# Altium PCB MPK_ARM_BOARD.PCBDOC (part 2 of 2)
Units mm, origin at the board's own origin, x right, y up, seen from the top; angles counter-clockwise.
Board outline 120 x 100 mm, 2 copper layers (Top Layer, Bottom Layer); 129 components, 139 nets, 526 pads, 161 vias.
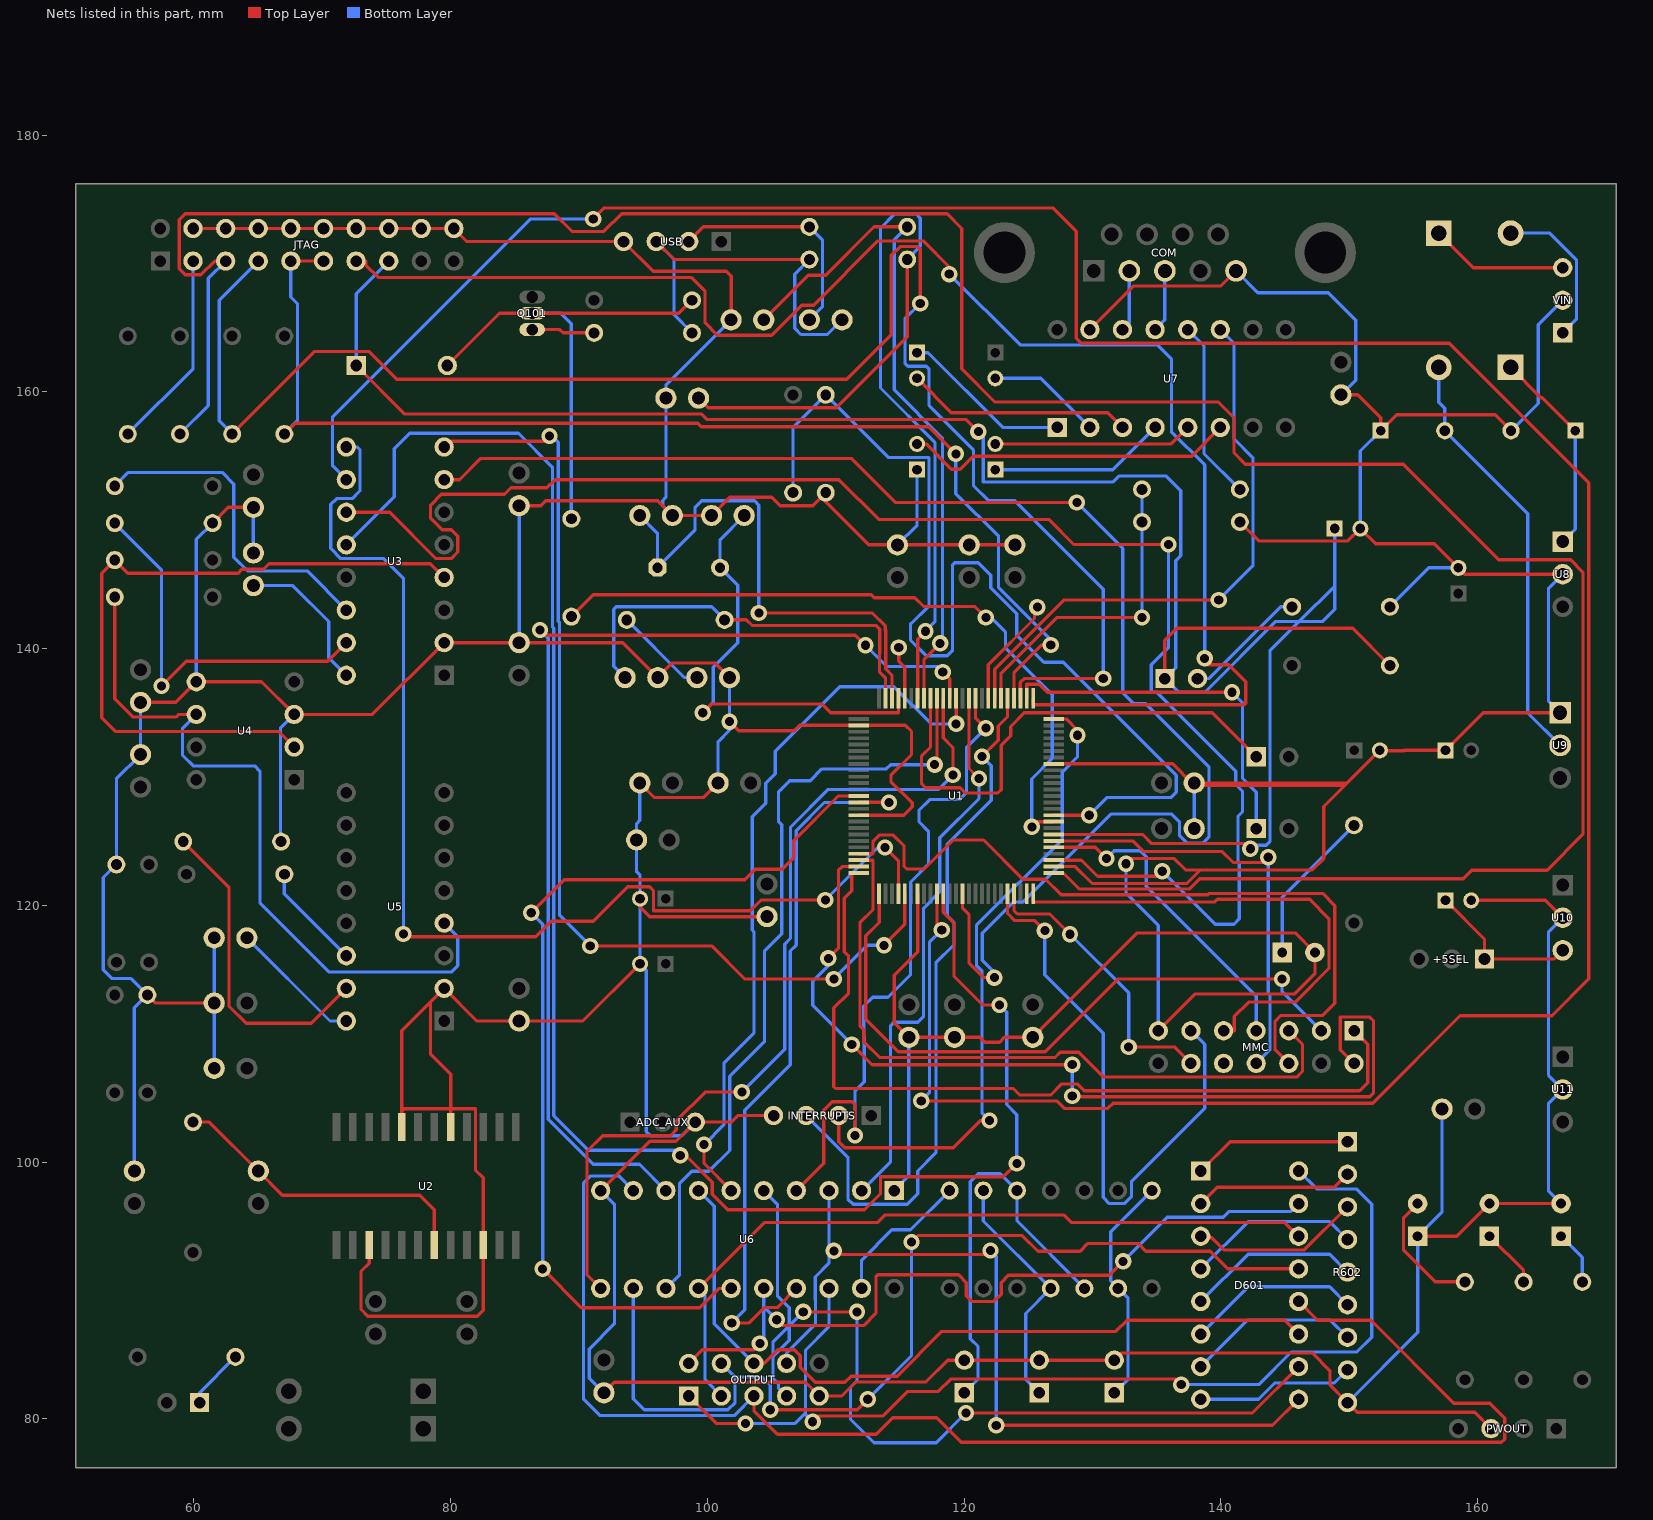
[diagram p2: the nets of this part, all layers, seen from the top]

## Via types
v1: diameter 1.27, hole 0.711, Top Layer to Bottom Layer, 161 vias

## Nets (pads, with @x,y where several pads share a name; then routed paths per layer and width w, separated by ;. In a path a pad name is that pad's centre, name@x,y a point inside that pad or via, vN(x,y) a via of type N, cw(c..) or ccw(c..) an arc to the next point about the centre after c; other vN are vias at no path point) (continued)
DAC_VRT_D2: U1.39 U3.7 | length 117.4
  Top Layer w0.254: U3.7@79.502,153.162 80.696,153.162 82.347,154.813 111.201,154.813 114.63,151.384 v1(128.778,151.384) ; U1.39@119.88,120.924 119.88,119.786 120.371,119.296 120.371,115.545 121.539,114.376 v1(122.352,114.376)
  Bottom Layer w0.254: v1(122.352,114.376) 122.352,114.783 121.412,115.722 121.412,117.831 123.85,120.269 124.612,120.269 131.47,127.127 136.144,127.127 136.779,126.492 136.779,125.425 137.363,124.841 138.582,124.841 139.065,125.324 139.065,130.81 134.163,135.712 133.198,135.712 132.359,136.55 132.359,147.803 v1(128.778,151.384)
DAC_VRT_D3: U1.30 U3.8 | length 79.7
  Top Layer w0.254: U3.8@79.502,155.702 79.502,156.159 87.3,156.159 v1(87.706,156.566) ; v1(90.881,116.84) 100.328,116.84 102.893,114.275 v1(109.855,114.275) ; v1(113.754,116.891) 115.38,118.516 U1.30@115.38,120.924
  Bottom Layer w0.254: v1(87.706,156.566) 87.884,156.566 88.392,156.058 88.392,142.138 88.494,142.037 88.494,119.228 v1(90.881,116.84) ; v1(109.855,114.275) 112.471,116.891 v1(113.754,116.891)
DAC_VRT_D4: U1.29 U3.9 | length 91.8
  Top Layer w0.254: v1(76.327,117.78) 76.556,117.551 86.639,117.551 87.859,118.77 91.11,118.77 93.802,121.463 95.504,121.463 95.809,121.158 95.809,119.583 103.353,119.583 104.191,120.421 v1(109.195,120.421) ; v1(113.843,124.511) 114.88,123.474 U1.29@114.88,120.924
  Bottom Layer w0.254: U3.9@71.882,155.702 72.746,155.702 72.949,155.499 72.949,152.298 72.339,151.689 71.12,151.689 70.663,151.232 70.663,147.806 71.454,147.015 74.803,147.015 76.327,145.491 v1(76.327,117.78) ; v1(109.195,120.421) 113.284,124.511 v1(113.843,124.511)
DAC_VRT_D5: U1.35 U3.10 | length 235.7
  Top Layer w0.254: v1(91.11,173.457) 91.973,174.32 126.898,174.32 128.727,172.491 128.727,164.186 129.134,163.779 157.785,163.779 168.656,152.908 168.656,114.275 165.786,111.404 158.623,111.404 151.816,104.597 131.597,104.597 131.191,104.191 127.787,104.191 127.203,104.775 v1(116.662,104.775) ; U1.35@117.88,120.924 117.88,118.467 v1(118.262,118.085)
  Bottom Layer w0.254: U3.10@71.882,153.162 70.815,154.229 70.815,158.064 86.208,173.457 v1(91.11,173.457) ; v1(116.662,104.775) 117.297,105.41 117.297,117.119 v1(118.262,118.085)
DAC_VRT_D6: U1.53 U3.11 | length 125.8
  Top Layer w0.254: U3.11@71.882,150.622 75.26,150.622 78.867,147.015 80.061,147.015 80.569,147.523 80.569,148.742 80.061,149.25 79.35,149.25 78.445,150.155 78.445,151.181 79.283,152.019 84.201,152.019 84.709,152.527 87.503,152.527 88.138,153.162 110.236,153.162 113.335,150.063 126.594,150.063 128.549,148.107 v1(135.915,148.107) ; U1.53@126.98,123.524 129.141,123.524 130.389,122.276 135.052,122.276 v1(135.433,122.657)
  Bottom Layer w0.254: v1(135.433,122.657) 139.548,118.542 141.021,118.542 141.427,118.948 141.427,123.368 141.326,123.469 141.326,126.924 141.681,127.279 141.681,128.905 141.148,129.438 141.148,130.464 135.011,136.601 134.579,136.601 134.579,138.735 135.915,140.071 v1(135.915,148.107)
DAC_VRT_D7: U1.36 U3.12 | length 139.6
  Top Layer w0.254: v1(97.892,100.533) 98.298,100.533 100.381,98.45 100.381,97.511 101.6,96.291 112.243,96.291 113.487,97.536 113.487,98.857 123.063,98.857 v1(124.104,99.898) ; U1.36@118.38,120.924 118.38,119.482 119.204,118.657 119.204,114.501 121.463,112.243 v1(122.758,112.243)
  Bottom Layer w0.254: U3.12@71.882,148.082 75.616,151.816 75.616,155.575 76.81,156.769 85.293,156.769 87.935,154.127 87.935,141.711 88.041,141.605 88.041,103.628 90.729,100.94 97.485,100.94 v1(97.892,100.533) ; v1(122.758,112.243) 123.319,111.682 123.319,104.493 124.104,103.708 v1(124.104,99.898)
ERASE: ERASE.1 U1.92 | length 39.8
  Top Layer w0.254: U1.92@117.38,136.124 117.38,132.334 116.688,131.642 116.688,129.464 116.992,129.159 119.685,129.159 120.091,128.753 122.631,128.753 122.885,129.007 122.885,132.461 123.622,133.198 123.622,133.934 124.689,135.001 139.319,135.001 ERASE.1@142.748,131.572
FIQ: INTERRUPTS.2 U1.75 | length 51.1
  Top Layer w0.254: INTERRUPTS.2@110.236,103.632 110.236,101.6 110.719,101.117 119.151,101.117 121.285,103.251 v1(121.971,103.251) ; U1.75@126.98,134.524 127.96,134.524 128.829,133.655 v1(128.829,133.248)
  Bottom Layer w0.254: v1(121.971,103.251) 121.387,103.835 121.387,114.91 120.955,115.341 120.955,118.44 127.635,125.12 127.635,130.378 128.829,131.572 v1(128.829,133.248)
GND: +3.3.2 +5.2 +8.2 -8.1 ADC_AUX.3 B1.2 B2.2 B3.2 C001.2 C002.2 C003.2 C004.2 C005.1 C006.1 C6.2 C007.1 C101.2 C102.2 C104.1 C105.1 C106.1 C107.1 C108.2 C109.2 C111.1 C112.1 C113.1 C114.1 C115.1 C116.1 C117.1 C118.1 C119.1 C120.1 C121.1 C122.1 C204.1 C301.1 C302.1 C303.2 C304.1 C401.1 C402.2 C501.1 C502.1 C503.2 C504.1 C601.1 C704.1 C705.1 COM.5 INTERRUPTS.4 JTAG.4 JTAG.6 JTAG.8 JTAG.10 JTAG.12 JTAG.14 JTAG.16 JTAG.18 JTAG.20 MMC.13 OUTPUT.9 PWOUT.3 R107.1 R113.1 R301.1 R404.1 R406.1 R501.1 R602.9 R702.1 U1.2 U1.16 U1.32 U1.52 U1.68 U1.83 U1.96 U2.3 U2.10 U2.17 U2.20 U3.2 U4.3 U4.5 U5.2 U6.1 U6.10 U7.15 U8.2 U9.1 U10.2 U11.2 USB.4 VIN.2 | length 911.7
  Top Layer w0.254: C401.1@55.855,135.814 58.598,135.814 U4.5@60.198,137.414 65.278,137.414 U4.3@67.818,134.874 73.914,134.874 U3.2@79.502,140.462 C304.1@85.344,140.462 93.421,140.462 C106.1@96.139,137.744 97.282,138.887 100.584,138.887 C107.1@101.727,137.744 ; R406.1@56.388,113.03 57.023,112.395 C502.1@61.595,112.395 ; JTAG.4@59.944,172.72 JTAG.6@62.484,172.72 JTAG.8@65.024,172.72 JTAG.10@67.564,172.72 JTAG.12@70.104,172.72 JTAG.14@72.644,172.72 JTAG.16@75.184,172.72 JTAG.18@77.724,172.72 JTAG.20@80.264,172.72 81.28,171.704 USB.4@93.472,171.704 95.783,169.393 101.473,169.393 101.854,169.012 C104.1@101.854,165.608 ; R301.1@61.468,149.775 62.696,151.003 C302.1@64.643,151.003 ; U2.3@73.66,93.543 73.66,92.126 73.025,91.491 73.025,88.544 73.558,88.011 82.093,88.011 82.55,88.468 U2.10@82.55,93.543 82.55,98.781 81.94,99.39 81.94,104.165 80.01,104.165 ; U2.20@76.2,102.743 76.2,103.962 ; U2.17@80.01,102.743 80.01,104.165 ; C303.2@85.344,151.13 87.02,151.13 87.401,151.511 96.139,151.511 C102.2@97.282,150.368 C101.2@100.33,150.368 101.752,151.79 105.004,151.79 105.664,151.13 108.204,151.13 R107.1@109.22,152.146 109.22,151.435 112.573,148.082 C112.1@114.808,148.082 C122.1@120.396,148.082 C117.1@123.952,148.082 ; U6.10@91.694,97.79 95.529,101.625 97.561,101.625 ADC_AUX.3@99.06,103.124 101.854,103.124 102.362,103.632 INTERRUPTS.4@105.156,103.632 ; C601.1@91.948,82.042 92.761,82.855 107.645,82.855 OUTPUT.9@108.712,81.788 110.465,81.788 111.557,82.88 117.018,82.88 118.72,84.582 B1.2@120.015,84.582 B2.2@125.857,84.582 B3.2@131.699,84.582 132.258,85.141 147.117,85.141 148.488,83.769 148.488,82.652 R602.9@149.86,81.28 150.622,80.518 159.766,80.518 PWOUT.3@161.036,79.248 ; C118.1@94.742,129.54 95.885,128.397 99.695,128.397 C111.1@100.838,129.54 ; C108.2@94.758,115.443 90.313,110.998 C504.1@85.344,110.998 82.042,110.998 U5.2@79.502,113.538 78.435,112.471 ; C109.2@94.758,120.523 94.758,119.872 95.504,119.126 C119.1@104.648,119.126 ; v1(101.727,134.315) 102.44,133.602 106.782,133.602 107.204,134.024 U1.2@111.78,134.024 115.429,134.024 115.9,133.553 115.9,131.75 114.3,130.15 114.3,129.642 115.951,127.991 115.951,127.686 115.289,127.024 U1.16@111.78,127.024 ; v1(114.91,140.081) 114.91,139.014 115.38,138.544 U1.96@115.38,136.124 ; U1.32@116.38,120.924 116.38,116.383 114.554,114.557 114.554,110.871 C113.1@115.697,109.728 C120.1@119.253,109.728 121.234,109.728 121.615,109.347 122.758,109.347 123.139,109.728 C115.1@125.349,109.728 133.477,117.856 145.796,117.856 +3.3.2@147.32,116.332 147.32,114.681 145.745,113.106 137.998,113.106 MMC.13@135.128,110.236 ; U1.83@121.88,136.124 121.88,138.746 125.48,142.346 v1@125.48,143.006 ; U1.52@126.98,123.024 128.651,123.024 129.968,121.707 137.338,121.707 138.389,122.758 ; U1.68@126.98,131.024 136.235,131.024 137.82,129.438 137.922,129.337 149.641,129.337 ; U7.15@129.794,164.846 133.198,168.25 140.006,168.25 COM.5@141.176,169.42 ; v1(132.613,123.241) 133.02,123.647 136.373,123.647 137.262,122.758 138.389,122.758 ; C121.1@137.922,129.54 149.844,129.54 ; R702.1@141.478,149.86 142.951,148.387 149.895,148.387 C6.2@150.86,149.352 152.054,148.158 156.626,148.158 C002.2@158.496,146.288 158.988,145.796 U8.2@166.624,145.796 ; C705.1@149.352,159.766 150.647,159.766 152.44,157.973 C005.1@152.44,156.972 153.685,158.217 161.355,158.217 C001.2@162.6,156.972 ; -8.1@155.321,94.234 158.369,94.234 +5.2@160.909,96.774 +8.2@166.497,96.774 ; C003.2@159.496,120.396 165.269,120.396 U10.2@166.624,119.041 ; U9.1@166.424,135.009 160.425,135.009 C006.1@157.496,132.079 154.28,132.079 154.255,132.055 152.384,132.055 C004.2@152.384,132.08 149.844,129.54 ; 76.2,103.962 76.403,104.165 80.01,104.165 ; 76.2,103.962 76.2,110.236 78.435,112.471 ; 78.435,112.471 78.435,108.433 80.01,106.858 80.01,104.165 ; 138.389,122.758 147.117,122.758 148.006,123.647 148.006,127.702 149.641,129.337 ; 149.641,129.337 149.844,129.54
  Bottom Layer w0.254: C204.1@55.372,99.314 55.372,112.014 R406.1@56.388,113.03 55.118,114.3 53.645,114.3 52.959,114.986 52.959,122.174 R404.1@53.975,123.19 53.975,129.87 C402.2@55.855,131.75 C401.1@55.855,135.814 ; U4.5@60.198,137.414 60.198,148.505 R301.1@61.468,149.775 ; C503.2@61.595,107.315 C502.1@61.595,112.395 C501.1@61.595,117.475 ; C301.1@64.643,147.447 C302.1@64.643,151.003 ; R501.1@66.802,124.968 66.751,124.968 66.751,133.807 U4.3@67.818,134.874 ; C304.1@85.344,140.462 C303.2@85.344,151.13 ; U6.10@91.694,97.79 92.761,96.723 92.761,87.401 90.805,85.446 90.805,83.185 C601.1@91.948,82.042 ; C118.1@94.742,129.54 94.742,126.619 94.488,126.365 C114.1@94.488,125.095 94.488,122.606 94.758,122.336 C109.2@94.758,120.523 C108.2@94.758,115.443 95.25,114.951 95.25,102.387 95.58,102.057 97.993,102.057 ADC_AUX.3@99.06,103.124 ; C102.2@97.282,150.368 96.52,151.13 96.52,151.536 96.774,151.79 C105.1@96.774,159.512 96.774,160.528 C104.1@101.854,165.608 ; C111.1@100.838,129.54 100.838,132.74 101.727,133.629 v1(101.727,134.315) C107.1@101.727,137.744 ; U6.1@114.554,97.79 115.697,98.933 C113.1@115.697,109.728 ; C112.1@114.808,148.082 116.332,149.606 C704.1@116.332,153.94 ; v1(132.613,123.241) 132.613,120.955 135.128,118.44 MMC.13@135.128,110.236 ; C116.1@137.922,125.984 C121.1@137.922,129.54 ; COM.5@141.176,169.42 142.88,167.716 148.361,167.716 150.495,165.583 150.495,160.909 C705.1@149.352,159.766 ; R602.9@149.86,81.28 155.321,86.741 -8.1@155.321,94.234 157.226,96.139 C007.1@157.226,104.14 ; C6.2@150.86,149.352 150.86,155.392 C005.1@152.44,156.972 ; R113.1@153.162,143.256 156.194,146.288 C002.2@158.496,146.288 ; C001.2@162.6,156.972 164.719,159.091 164.719,165.227 VIN.2@166.624,167.132 ; U9.1@166.424,135.009 165.506,135.926 165.506,144.678 U8.2@166.624,145.796 ; +8.2@166.497,96.774 165.506,97.765 165.506,104.546 U11.2@166.624,105.664 165.506,106.782 165.506,117.924 U10.2@166.624,119.041
  other v1: 125.705,143.231
IRQ: INTERRUPTS.3 U1.80 | length 56.3
  Top Layer w0.254: v1(121.387,131.597) 122.657,132.867 122.657,133.973 123.38,134.696 U1.80@123.38,136.124
  Bottom Layer w0.254: INTERRUPTS.3@107.696,103.632 110.947,100.381 110.947,97.13 111.354,96.723 115.57,96.723 116.383,97.536 116.383,99.314 117.805,100.736 117.805,115.536 119.211,116.942 119.211,118.686 118.694,119.202 118.694,124.765 122.116,128.187 122.116,130.868 v1(121.387,131.597)
JTAG_JTAGSEL: JTAGSEL.1 U1.77 | length 28.8
  Top Layer w0.254: U1.77@124.88,136.124 124.88,137.231 125.857,137.231 126.487,136.601 v1(140.868,136.601)
  Bottom Layer w0.254: v1(140.868,136.601) 141.681,135.788 141.681,129.896 142.748,128.829 JTAGSEL.1@142.748,125.984
JTAG_TCK: JTAG.9 JTAG.11 R111.1 U1.79 | length 94
  Top Layer w0.254: R111.1@67.056,156.718 67.894,157.556 99.263,157.556 99.543,157.277 117.246,157.277 v1(119.355,155.169) ; JTAG.9@67.564,170.18 JTAG.11@70.104,170.18 ; U1.79@123.88,136.124 123.88,138.125 126.039,140.284 v1(126.746,140.284)
  Bottom Layer w0.254: R111.1@67.056,156.718 68.072,157.734 68.072,166.878 67.564,167.386 JTAG.9@67.564,170.18 ; v1(119.355,155.169) 119.355,152.07 122.682,148.742 122.682,144.755 126.746,140.691 v1(126.746,140.284)
JTAG_TDI: JTAG.5 R109.1 U1.51 | length 217.1
  Top Layer w0.254: JTAG.5@62.484,170.18 61.62,170.18 60.554,169.113 59.334,169.113 58.877,169.57 58.877,173.406 59.334,173.863 88.087,173.863 89.459,172.491 91.948,172.491 93.32,173.863 118.669,173.863 119.812,172.72 119.812,161.798 122.403,159.207 139.802,159.207 141.021,157.988 141.021,155.245 141.91,154.356 154.203,154.356 161.646,146.914 167.234,146.914 168.199,145.948 168.199,125.527 165.405,122.733 159.537,122.733 158.877,122.072 138.34,122.072 137.541,121.273 128.988,121.273 127.737,122.524 U1.51@126.98,122.524
  Bottom Layer w0.254: R109.1@58.928,156.718 61.138,158.928 61.138,168.834 JTAG.5@62.484,170.18
JTAG_TDO: JTAG.13 U1.76 | length 121.9
  Top Layer w0.254: JTAG.13@72.644,170.18 73.406,170.18 73.406,169.875 74.371,168.91 98.73,168.91 99.822,167.818 99.822,165.379 100.787,164.414 105.004,164.414 107.34,166.751 108.28,166.751 113.284,171.755 116.815,171.755 118.847,169.723 v1(118.847,169.164) ; U1.76@125.38,136.124 125.38,135.636 141.834,135.636 141.935,135.738 141.935,137.414 140.614,138.735 138.989,138.735 138.735,138.989 v1(138.735,139.243)
  Bottom Layer w0.254: v1(118.847,169.164) 124.358,163.652 135.052,163.652 136.144,162.56 136.144,156.896 138.735,154.305 v1(138.735,139.243)
JTAG_TMS: JTAG.7 R110.1 U1.78 | length 130.5
  Top Layer w0.254: R110.1@62.992,156.718 69.418,163.144 73.635,163.144 75.794,160.985 110.871,160.985 114.325,164.44 114.325,170.628 115.011,171.314 116.366,171.314 116.586,171.094 v1(116.586,166.878) ; U1.78@124.38,136.124 124.38,137.363 124.685,137.668 v1(130.835,137.668)
  Bottom Layer w0.254: R110.1@62.992,156.718 61.976,157.734 61.976,167.132 JTAG.7@65.024,170.18 ; v1(116.586,166.878) 115.392,165.684 115.392,162.23 115.621,162.001 117.043,162.001 117.272,161.773 117.272,158.928 120.726,155.473 120.726,152.705 121.92,151.511 123.952,151.511 130.835,144.628 v1(130.835,137.668)
MISO0: MMC.2 U1.24 | length 73.6
  Top Layer w0.254: v1(109.423,115.875) 110.211,116.662 110.211,122.733 110.502,123.024 U1.24@111.78,123.024 ; v1(111.252,109.169) 112.827,107.594 v1(128.422,107.594) ; v1(128.422,105.156) 128.473,105.105 151.587,105.105 151.892,105.41 151.892,110.998 151.587,111.303 149.301,111.303 149.301,108.763 MMC.2@150.368,107.696
  Bottom Layer w0.254: v1(109.423,115.875) 109.423,115.316 108.202,114.095 108.202,112.219 v1(111.252,109.169) ; v1(128.422,105.156) v1(128.422,107.594)
MISO1: MMC.8 U1.56 | length 34.1
  Top Layer w0.254: U1.56@126.98,125.024 133.142,125.024 133.96,124.206 140.081,124.206 140.945,123.342 143.281,123.342 v1(143.688,123.749)
  Bottom Layer w0.254: MMC.8@142.748,107.696 143.815,108.763 143.815,113.03 143.688,113.157 v1(143.688,123.749)
MMC_CP: MMC.6 U1.22 | length 60
  Top Layer w0.254: U1.22@111.78,124.024 112.901,124.024 112.901,124.97 113.407,125.476 114.482,125.476 115.316,124.642 115.316,123.038 115.519,122.834 116.891,122.834 119.151,125.095 121.514,125.095 124.562,122.047 126.34,122.047 127.559,120.828 138.989,120.828 139.09,120.929 147.93,120.929 148.869,119.99 148.869,112.37 147.93,111.43 144.678,111.43 144.221,110.973 144.221,108.763 MMC.6@145.288,107.696
MMC_WP: MMC.5 U1.23 | length 55.2
  Top Layer w0.254: U1.23@111.78,123.524 112.903,123.524 112.903,119.659 111.887,118.643 111.887,110.617 112.192,110.312 112.192,109.398 113.436,108.153 127.076,108.153 127.483,108.56 128.93,108.56 130.861,106.629 145.898,106.629 146.355,107.086 146.355,109.169 MMC.5@145.288,110.236
MOSI0: MMC.1 U1.25 | length 65.2
  Top Layer w0.254: U1.25@111.78,122.524 111.252,122.524 111.252,121.133 110.668,120.548 110.668,116.385 110.998,116.055 110.998,113.159 109.853,112.014 109.853,105.867 109.982,105.738 123.827,105.738 124.333,105.232 126.744,105.232 127.61,106.098 128.827,106.098 129.362,105.562 150.8,105.562 151.435,106.197 151.435,109.169 MMC.1@150.368,110.236
MOSI1: MMC.7 U1.55 | length 25.1
  Top Layer w0.254: U1.55@126.98,124.524 130.213,124.524 v1(131.089,123.647)
  Bottom Layer w0.254: v1(131.089,123.647) 131.699,124.257 133.733,124.257 134.188,123.802 134.188,121.488 142.748,112.928 MMC.7@142.748,110.236
Net+5V_SELECT_1: +5SEL.1 C003.1 U10.3 | length 12.2
  Top Layer w0.254: C003.1@157.496,120.396 160.528,117.364 +5SEL.1@160.528,115.824 165.947,115.824 U10.3@166.624,116.501
NetB1_1: B1.1 R114.1 R115.2 | length 31.4
  Bottom Layer w0.254: B1.1@120.015,82.042 121.082,83.109 121.082,85.649 120.472,86.258 120.472,98.476 121.107,99.111 122.801,99.111 R115.2@124.121,97.79 124.121,95.419 R114.1@129.371,90.17
NetB2_1: B2.1 R116.1 R117.2 | length 19.2
  Bottom Layer w0.254: R117.2@121.497,97.79 121.497,95.419 R116.1@126.746,90.17 124.79,88.214 124.79,83.109 B2.1@125.857,82.042
NetB3_1: B3.1 R118.1 R119.2 | length 18.1
  Bottom Layer w0.254: B3.1@131.699,82.042 132.766,83.109 132.766,89.4 R118.1@131.995,90.17 131.42,90.746 131.42,94.59 R119.2@134.62,97.79
NetC001_1: C001.1 D001.2 U8.1 | length 16.1
  Top Layer w0.254: D001.2@162.56,161.902 164.925,159.537 165.035,159.537 C001.1@167.6,156.972
  Bottom Layer w0.254: U8.1@166.624,148.336 167.6,149.312 C001.1@167.6,156.972
NetC005_2: C005.2 D002.1 U9.3 | length 33.3
  Bottom Layer w0.254: D002.1@156.972,161.902 156.972,159.182 157.44,158.714 C005.2@157.44,156.972 163.906,150.506 163.906,134.986 U9.3@166.424,132.469
NetC101_1: C101.1 U1.97 X1.2 | length 34.8
  Top Layer w0.254: v1(99.644,135.001) 100.334,135.691 108.911,135.691 109.601,135.001 114.88,135.001 U1.97@114.88,136.124
  Bottom Layer w0.254: v1(99.644,135.001) 100.457,135.814 100.457,138.557 102.362,140.462 102.362,144.934 X1.2@100.992,146.304 100.992,148.49 C101.1@102.87,150.368
NetC102_1: C102.1 U1.98 X1.1 | length 40.4
  Top Layer w0.254: v1(104.013,142.773) 112.852,142.773 113.862,141.763 113.862,141.458 113.894,141.427 113.894,138.43 114.38,137.944 U1.98@114.38,136.124
  Bottom Layer w0.254: C102.1@94.742,150.368 96.112,148.998 X1.1@96.112,146.304 99.035,149.227 99.035,150.978 99.568,151.511 103.683,151.511 104.013,151.181 v1(104.013,142.773)
NetC103_1: C103.1 R102.2 USB.2 | length 18
  Top Layer w0.254: USB.2@98.552,171.704 99.695,172.847 R102.2@107.95,172.847
  Bottom Layer w0.254: C103.1@107.95,165.608 108.966,166.624 108.966,171.831 R102.2@107.95,172.847
NetC103_2: C103.2 R101.2 R103.1 USB.3 | length 31
  Top Layer w0.254: USB.3@96.012,171.704 97.409,170.307 R101.2@107.95,170.307
  Bottom Layer w0.254: USB.3@96.012,171.704 97.409,170.307 97.409,165.989 R103.1@98.806,164.592 ; R101.2@107.95,170.307 106.807,169.164 106.807,164.948 107.29,164.465 109.347,164.465 C103.2@110.49,165.608
NetC104_2: C104.2 R102.1 U1.93 | length 53.5
  Top Layer w0.254: C104.2@104.394,165.608 107.874,169.088 109.22,169.088 112.979,172.847 R102.1@115.57,172.847 ; U1.93@116.88,136.124 116.88,139.156 v1(118.135,140.411)
  Bottom Layer w0.254: R102.1@115.57,172.847 114.554,171.831 114.554,160.147 118.313,156.388 118.313,140.589 v1(118.135,140.411)
NetC105_2: C105.2 R101.1 U1.94 | length 71.2
  Top Layer w0.254: C105.2@99.314,159.512 100.076,158.75 110.033,158.75 115.57,164.287 R101.1@115.57,170.307 ; U1.94@116.38,136.124 116.38,140.739 v1(116.992,141.351)
  Bottom Layer w0.254: R101.1@115.57,170.307 116.586,171.323 116.586,173.533 116.256,173.863 114.605,173.863 113.487,172.745 113.487,160.299 117.729,156.058 117.729,142.088 v1(116.992,141.351)
NetC106_2: C106.2 R120.2 U1.99 | length 32.8
  Top Layer w0.254: R120.2@101.346,142.24 103.048,142.24 103.48,141.808 113.132,141.808 113.428,141.511 113.428,139.616 113.411,139.598 113.411,138.176 113.88,137.707 U1.99@113.88,136.124
  Bottom Layer w0.254: C106.2@93.599,137.744 92.71,138.633 92.71,143.053 92.913,143.256 100.33,143.256 R120.2@101.346,142.24
NetC107_2: C107.2 R120.1 | length 7.3
  Bottom Layer w0.254: R120.1@93.726,142.24 98.222,137.744 C107.2@99.187,137.744
NetC205_2: C205.2 L212.2 U2.7 | length 24.4
  Top Layer w0.254: L212.2@59.944,103.124 61.214,103.124 C205.2@65.024,99.314 66.904,97.434 77.597,97.434 78.74,96.291 U2.7@78.74,93.543
NetC301_2: C301.2 U3.16 | length 11.8
  Bottom Layer w0.254: C301.2@64.643,144.907 67.716,144.907 70.51,142.113 70.51,139.294 U3.16@71.882,137.922
NetC501_2: C501.2 U5.16 | length 10.4
  Bottom Layer w0.254: C501.2@64.135,117.475 70.612,110.998 U5.16@71.882,110.998
NetC701_1: C701.1 U7.1 | length 13.3
  Bottom Layer w0.254: C701.1@116.332,163.052 117.186,163.052 123.012,157.226 U7.1@127.254,157.226
NetC701_2: C701.2 U7.3 | length 17.6
  Top Layer w0.254: C701.2@116.332,161.052 119.015,158.369 131.191,158.369 U7.3@132.334,157.226
NetC702_1: C702.1 U7.4 | length 13.8
  Bottom Layer w0.254: C702.1@122.428,153.94 131.588,153.94 U7.4@134.874,157.226
NetC702_2: C702.2 U7.5 | length 15.5
  Top Layer w0.254: C702.2@122.428,155.94 136.128,155.94 U7.5@137.414,157.226
NetC703_2: C703.2 U7.2 | length 9
  Bottom Layer w0.254: C703.2@122.428,161.052 125.968,161.052 U7.2@129.794,157.226
NetC704_2: C704.2 U7.6 | length 25.8
  Top Layer w0.254: C704.2@116.332,155.94 117.043,155.94 119.008,153.975 119.685,153.975 120.701,154.991 137.719,154.991 U7.6@139.954,157.226
NetD001_1: D001.1 VIN.1 | length 12.1
  Bottom Layer w0.254: D001.1@162.56,172.362 165.61,172.362 167.691,170.282 167.691,165.659 VIN.1@166.624,164.592
NetD002_2: D002.2 VIN.3 | length 10.8
  Top Layer w0.254: D002.2@156.972,172.362 159.662,169.672 VIN.3@166.624,169.672
NetD101_1: D101.1 Q101.2 R104.1 R105.2 | length 39.7
  Top Layer w0.254: D101.1@79.75,162.052 83.814,166.116 Q101.2@86.36,166.116 97.79,166.116 R104.1@98.806,167.132
  Bottom Layer w0.254: Q101.2@86.36,166.116 88.595,166.116 89.408,165.303 R105.2@89.408,150.114
NetD601_1: D601.1 R602.1 | length 12.4
  Top Layer w0.254: D601.1@138.43,99.314 140.716,101.6 R602.1@149.86,101.6
NetD601_2: D601.2 R602.2 | length 12.4
  Top Layer w0.254: D601.2@138.43,96.774 139.7,98.044 148.844,98.044 R602.2@149.86,99.06
NetD601_3: D601.3 R602.3 | length 13.3
  Top Layer w0.254: D601.3@138.43,94.234 138.43,94.107 139.294,94.107 140.233,93.167 146.507,93.167 R602.3@149.86,96.52
NetD601_4: D601.4 R602.4 | length 13.5
  Bottom Layer w0.254: D601.4@138.43,91.694 142.113,95.377 148.463,95.377 R602.4@149.86,93.98
NetD601_5: D601.5 R602.5 | length 13.5
  Bottom Layer w0.254: D601.5@138.43,89.154 142.113,92.837 148.463,92.837 R602.5@149.86,91.44
NetD601_6: D601.6 R602.6 | length 13.5
  Bottom Layer w0.254: D601.6@138.43,86.614 142.113,90.297 148.463,90.297 R602.6@149.86,88.9
NetD601_7: D601.7 R602.7 | length 13.5
  Bottom Layer w0.254: D601.7@138.43,84.074 142.062,87.706 148.514,87.706 R602.7@149.86,86.36
NetD601_8: D601.8 R602.8 | length 12.4
  Bottom Layer w0.254: D601.8@138.43,81.534 142.926,81.534 144.196,82.804 148.844,82.804 R602.8@149.86,83.82
NetJ1_2: COM.2 U7.14 | length 4.8
  Bottom Layer w0.254: U7.14@132.334,164.846 132.866,165.378 COM.2@132.866,169.42
NetJ1_3: COM.3 U7.13 | length 4.9
  Bottom Layer w0.254: U7.13@134.874,164.846 135.636,165.608 COM.3@135.636,169.42
NetJTAG_3: JTAG.3 R108.1 | length 15.6
  Bottom Layer w0.254: R108.1@54.864,156.718 59.944,161.798 JTAG.3@59.944,170.18
NetPW+3.3_1: +3.3.1 R003.1 | length 12.2
  Bottom Layer w0.254: +3.3.1@144.78,116.332 144.78,120.65 R003.1@150.368,126.238
NetPW+5_1: +5.1 R002.1 | length 4.7
  Top Layer w0.254: +5.1@160.909,94.234 163.576,91.567 R002.1@163.576,90.678
NetPW+8_1: +8.1 R001.1 | length 4.2
  Bottom Layer w0.254: +8.1@166.497,94.234 168.148,92.583 R001.1@168.148,90.678
NetPW-8_2: -8.2 R004.1 | length 9.9
  Top Layer w0.254: -8.2@155.321,96.774 154.229,95.682 154.229,93.142 156.693,90.678 R004.1@159.004,90.678
NetQ101_1: Q101.1 R103.2 | length 4.9
  Top Layer w0.254: Q101.1@86.36,164.846 88.519,164.846 88.773,164.592 R103.2@91.186,164.592
NetR113_2: R113.2 RESET.2 | length 9.7
  Bottom Layer w0.254: RESET.2@138.176,137.668 139.065,137.668 144.653,143.256 R113.2@145.542,143.256
NetR201_1: "SIG IN.1" R201.1 | length 4.7
  Bottom Layer w0.254: 60.452,81.28 60.452,82.042 R201.1@63.246,84.836
NetR301_2: R301.2 U3.15 | length 30
  Top Layer w0.254: v1(57.48,137.084) 59.411,139.014 70.434,139.014 U3.15@71.882,140.462
  Bottom Layer w0.254: R301.2@53.848,149.775 57.48,146.143 v1(57.48,137.084)
NetR302_2: R302.2 U3.14 | length 26.2
  Bottom Layer w0.254: R302.2@53.848,152.654 54.915,153.721 62.205,153.721 63.119,152.806 63.119,147.117 64.186,146.05 68.834,146.05 U3.14@71.882,143.002
NetR401_2: R401.2 U4.6 U5.4 | length 57
  Top Layer w0.254: R401.2@53.848,144.018 53.848,136.093 55.27,134.671 58.623,134.671 58.826,134.874 U4.6@60.198,134.874
  Bottom Layer w0.254: U4.6@60.198,134.874 59.131,133.807 59.131,131.674 59.944,130.861 64.745,130.861 65.151,130.454 65.151,120.218 70.561,114.808 80.061,114.808 80.569,115.316 80.569,117.551 U5.4@79.502,118.618
NetR402_2: R402.2 U3.4 U4.2 | length 55.5
  Top Layer w0.254: U4.2@67.818,132.334 66.599,133.553 53.899,133.553 52.832,134.62 52.832,145.881 R402.2@53.848,146.897 54.872,145.872 63.449,145.872 63.754,146.177 65.43,146.177 65.862,146.609 78.435,146.609 U3.4@79.502,145.542
NetR501_2: R501.2 U5.15 | length 25.1
  Top Layer w0.254: R501.2@59.182,124.968 62.738,121.412 62.738,112.166 64.084,110.82 69.164,110.82 U5.15@71.882,113.538
NetR502_2: R502.2 U5.14 | length 8.3
  Bottom Layer w0.254: R502.2@67.056,122.428 67.056,120.904 U5.14@71.882,116.078
NetR601_1: R601.1 U6.19 | length 11.3
  Bottom Layer w0.254: U6.19@112.014,90.17 112.014,92.38 114.376,94.742 115.824,94.742 R601.1@118.872,97.79
NetR701_1: R701.1 U7.12 | length 14.1
  Bottom Layer w0.254: U7.12@137.414,164.846 138.684,163.576 138.684,155.194 R701.1@141.478,152.4
OUT_0: U1.86 U6.2 | length 43.5
  Top Layer w0.254: U1.86@120.38,136.124 120.38,130.664 v1(121.158,129.886)
  Bottom Layer w0.254: U6.2@112.014,97.79 114.275,100.051 114.275,110.642 114.529,110.896 116.383,110.896 116.84,111.354 116.84,119.793 118.11,121.063 118.11,125.273 121.158,128.321 v1(121.158,129.886)
OUT_1: U1.85 U6.4 | length 53.6
  Top Layer w0.254: U6.4@106.934,97.79 109.068,99.924 109.068,104.038 109.728,104.699 111.277,104.699 111.506,104.47 v1(111.506,102.083) ; U1.85@120.88,136.124 120.88,134.619 v1(121.691,133.807)
  Bottom Layer w0.254: v1(111.506,102.083) 111.506,105.562 112.217,106.274 112.217,109.728 112.192,109.753 112.192,112.166 112.878,112.852 114.071,112.852 115.824,114.605 115.824,121.818 117.223,123.218 117.223,125.779 116.484,126.517 116.484,127.406 117.323,128.245 119.609,128.245 120.193,128.829 120.193,132.309 v1(121.691,133.807)
OUT_2: U1.88 U6.6 | length 56.9
  Top Layer w0.254: v1(99.746,101.371) 99.746,99.898 U6.6@101.854,97.79 ; v1(119.38,134.137) U1.88@119.38,136.124
  Bottom Layer w0.254: v1(99.746,101.371) 101.295,102.921 101.295,107.721 103.632,110.058 103.632,117.958 103.505,118.085 103.505,126.898 104.546,127.94 104.546,129.515 105.283,130.251 105.283,132.004 110.314,137.035 114.529,137.035 117.426,134.137 v1(119.38,134.137)
OUT_3: U1.89 U6.8 | length 84.8
  Top Layer w0.254: v1(86.97,141.453) 87.376,141.046 111.531,141.046 v1(112.319,140.259) ; v1(118.339,138.184) 118.88,137.643 U1.89@118.88,136.124
  Bottom Layer w0.254: v1(86.97,141.453) 87.607,140.815 87.607,103.353 91.112,99.847 94.717,99.847 U6.8@96.774,97.79 ; v1(112.319,140.259) 113.97,138.608 117.915,138.608 v1(118.339,138.184)
OUT_4: U1.90 U6.11 | length 68.3
  Top Layer w0.254: U6.11@91.694,90.17 90.627,91.237 90.627,100.848 91.846,102.067 97.13,102.067 97.587,102.524 97.587,103.226 99.822,105.461 v1(102.692,105.461) ; U1.90@118.38,136.124 118.38,133.045 119.126,132.299 v1(119.126,130.15)
  Bottom Layer w0.254: v1(102.692,105.461) 106.02,108.788 106.02,116.967 106.477,117.424 106.477,126.086 109.423,129.032 118.008,129.032 v1(119.126,130.15)
OUT_5: U1.91 U6.13 | length 61.6
  Top Layer w0.254: v1(117.705,130.962) 117.88,131.137 U1.91@117.88,136.124
  Bottom Layer w0.254: U6.13@96.774,90.17 97.841,91.237 97.841,98.349 98.781,99.289 100.127,99.289 101.75,100.912 101.75,106.68 104.445,109.375 104.445,116.434 105.791,117.78 105.791,126.289 105.537,126.543 105.537,128.829 106.426,129.718 108.011,129.718 108.925,130.632 113.944,130.632 114.275,130.962 v1(117.705,130.962)
OUT_6: U1.13 U6.15 | length 74.7
  Top Layer w0.254: v1(86.284,119.431) 88.849,121.996 102.921,121.996 103.734,122.809 105.842,122.809 106.731,123.698 106.731,125.04 110.215,128.524 U1.13@111.78,128.524 ; v1(87.173,91.694) 90.195,88.671 99.416,88.671 100.914,90.17 U6.15@101.854,90.17
  Bottom Layer w0.254: v1(86.284,119.431) 87.173,118.542 v1(87.173,91.694)
OUT_7: U1.14 U6.17 | length 57.1
  Top Layer w0.254: v1(101.905,87.478) 103.249,87.478 104.445,88.674 105.438,88.674 U6.17@106.934,90.17 ; U1.14@111.78,128.024 v1@114.14,128.024 ; 113.309,128.024 113.317,128.016 ; v1@114.14,128.016 v1(114.148,128.016)
  Bottom Layer w0.254: v1(101.905,87.478) 102.921,88.494 102.921,104.038 106.466,107.583 106.466,116.448 106.927,116.909 106.927,125.825 109.118,128.016 v1(114.148,128.016)
OUT_H_0: D601.16 OUTPUT.1 U6.18 | length 85.4
  Top Layer w0.254: OUTPUT.1@98.552,81.788 100.686,79.654 v1(102.972,79.654) ; v1(108.204,79.781) 108.661,80.239 113.69,80.239 115.595,82.144 117.983,82.144 118.948,83.109 136.474,83.109 v1(136.906,82.677)
  Bottom Layer w0.254: v1(102.972,79.654) 106.832,79.654 107.582,80.404 ; v1(108.204,79.781) 107.582,80.404 ; U6.18@109.474,90.17 109.474,87.198 107.645,85.369 107.645,80.467 107.582,80.404 ; v1(136.906,82.677) 142.951,82.677 145.491,85.217 150.597,85.217 151.74,86.36 151.74,96.723 150.546,97.917 147.447,97.917 D601.16@146.05,99.314
OUT_H_1: D601.15 OUTPUT.2 U6.16 | length 61.3
  Top Layer w0.254: OUTPUT.2@98.552,84.328 99.619,85.395 103.607,85.395 v1(104.089,85.877) ; v1(105.41,87.732) 105.867,87.274 112.166,87.274 113.132,88.24 113.132,91.075 113.284,91.227 119.568,91.227 120.167,90.627 120.167,89.595 120.608,89.154 122.317,89.154 122.885,89.722 122.885,90.627 123.444,91.186 131.293,91.186 v1(132.385,92.278)
  Bottom Layer w0.254: v1(104.089,85.877) 104.394,86.182 104.394,88.748 ; U6.16@104.394,90.17 104.394,88.748 ; v1(105.41,87.732) 104.394,88.748 ; v1(132.385,92.278) 135.814,95.707 140.183,95.707 140.64,96.164 145.44,96.164 D601.15@146.05,96.774
OUT_H_2: D601.14 OUTPUT.3 U6.14 | length 58.9
  Top Layer w0.254: U6.14@99.314,90.17 104.445,95.301 113.233,95.301 113.817,95.885 127.787,95.885 128.372,95.301 144.983,95.301 D601.14@146.05,94.234
  Bottom Layer w0.254: U6.14@99.314,90.17 99.822,89.662 99.822,83.058 OUTPUT.3@101.092,81.788
OUT_H_3: D601.13 OUTPUT.4 U6.12 | length 79
  Top Layer w0.254: v1(104.902,80.723) 111.686,80.723 v1(112.497,81.534) ; v1(115.9,93.777) 116.408,94.285 124.536,94.285 125.755,93.066 129.032,93.066 129.642,93.675 133.553,93.675 134.163,93.066 139.167,93.066 140.538,91.694 D601.13@146.05,91.694
  Bottom Layer w0.254: U6.12@94.234,90.17 94.234,81.585 95.098,80.721 101.6,80.721 102.159,81.28 102.159,83.261 ; OUTPUT.4@101.092,84.328 102.159,83.261 ; v1(104.902,80.723) 104.902,82.652 104.292,83.261 102.159,83.261 ; v1(112.497,81.534) 115.9,84.938 v1(115.9,93.777)
OUT_H_4: D601.12 OUTPUT.5 U6.9 | length 119.1
  Top Layer w0.254: OUTPUT.5@103.632,81.788 103.632,80.645 105.461,78.816 113.157,78.816 114.427,80.086 117.856,80.086 119.761,78.181 161.849,78.181 162.103,78.435 162.103,80.061 160.934,81.229 158.14,81.229 151.689,87.681 147.523,87.681 D601.12@146.05,89.154
  Bottom Layer w0.254: U6.9@94.234,97.79 93.091,98.933 90.932,98.933 90.348,98.349 90.348,81.585 91.669,80.264 102.108,80.264 OUTPUT.5@103.632,81.788
OUT_H_5: D601.11 OUTPUT.6 U6.7 | length 62.1
  Top Layer w0.254: OUTPUT.6@103.632,84.328 104.419,84.328 105.486,85.395 106.782,85.395 107.239,84.938 107.239,84.023 108.407,82.855 110.719,82.855 111.201,83.337 114.783,83.337 118.262,86.817 131.826,86.817 132.69,87.681 144.983,87.681 D601.11@146.05,86.614
  Bottom Layer w0.254: U6.7@99.314,97.79 100.533,96.571 100.533,87.427 OUTPUT.6@103.632,84.328
OUT_H_6: D601.10 OUTPUT.7 U6.5 | length 73.1
  Top Layer w0.254: v1(107.467,88.341) v1(111.658,88.341) ; v1(120.142,80.467) 142.443,80.467 D601.10@146.05,84.074
  Bottom Layer w0.254: U6.5@104.394,97.79 105.461,96.723 105.461,89.586 106.375,88.671 106.375,87.249 ; OUTPUT.7@106.172,81.788 105.537,82.423 105.537,82.753 105.105,83.185 105.105,84.861 ; v1(107.467,88.341) 106.375,87.249 ; v1(111.658,88.341) 111.658,82.984 111.15,82.476 111.15,79.985 112.979,78.156 117.831,78.156 v1(120.142,80.467) ; 105.105,84.861 105.105,85.979 106.375,87.249 ; 105.105,84.861 106.375,86.131 106.375,87.249
OUT_H_7: D601.9 OUTPUT.8 U6.3 | length 66
  Top Layer w0.254: v1(109.855,93.091) 110.134,92.812 121.742,92.812 v1(122.047,93.116) ; v1(122.504,79.502) 144.018,79.502 D601.9@146.05,81.534
  Bottom Layer w0.254: OUTPUT.8@106.172,84.328 106.172,85.141 108.433,87.401 108.433,89.256 108.407,89.281 108.407,91.059 109.474,92.126 109.474,93.091 v1@109.474,93.472 ; U6.3@109.474,97.79 v1@109.474,93.472 ; v1(109.855,93.091) v1@109.474,93.472 ; v1(122.047,93.116) 122.504,92.659 v1(122.504,79.502)
PA19: MMC.11 U1.46 | length 46
  Top Layer w0.254: U1.46@123.38,120.924 123.38,119.393 123.952,118.821 125.501,118.821 v1(126.289,118.034)
  Bottom Layer w0.254: v1(126.289,118.034) 126.289,114.605 130.835,110.058 130.835,97.257 131.318,96.774 132.486,96.774 133.045,97.333 133.045,98.527 138.735,104.216 138.735,109.169 MMC.11@137.668,110.236
PA20: MMC.12 U1.47 | length 22.5
  Top Layer w0.254: U1.47@123.88,120.924 123.88,119.604 124.155,119.329 126.67,119.329 v1(128.245,117.754) ; v1(132.817,108.966) 136.398,108.966 MMC.12@137.668,107.696
  Bottom Layer w0.254: v1(128.245,117.754) 132.817,113.182 v1(132.817,108.966)
RST: C6.1 D101.2 JTAG.15 R112.1 RESET.1 U1.57 | length 179.3
  Top Layer w0.254: D101.2@72.65,162.052 76.435,158.267 99.558,158.267 99.989,157.836 120.167,157.836 v1(121.107,156.896) ; U1.57@126.98,125.524 133.912,125.524 134.62,124.816 141.884,124.816 v1(142.291,124.409) ; RESET.1@135.636,137.668 135.636,140.64 136.576,141.58 150.266,141.58 R112.1@153.162,138.684
  Bottom Layer w0.254: D101.2@72.65,162.052 72.65,167.646 JTAG.15@75.184,170.18 ; v1(121.107,156.896) 121.488,156.515 121.488,152.984 131.597,152.984 132.055,153.441 135.738,153.441 136.881,152.298 136.881,147.244 136.474,146.837 136.474,138.506 RESET.1@135.636,137.668 136.703,136.601 138.76,136.601 144.279,142.12 146.107,142.12 ; v1(142.291,124.409) 142.57,124.689 143.535,124.689 143.815,124.968 143.815,139.827 146.107,142.12 ; C6.1@148.86,149.352 148.86,144.872 ; 146.107,142.12 147.93,142.12 148.86,143.05 148.86,144.872 ; 146.107,142.12 148.86,144.872
RXD0: R701.2 R702.2 U1.81 | length 24.7
  Top Layer w0.254: U1.81@122.88,136.124 122.88,138.095 127.203,142.418 v1(133.858,142.418)
  Bottom Layer w0.254: v1(133.858,142.418) R702.2@133.858,149.86 R701.2@133.858,152.4
SCK0: MMC.3 U1.26 | length 51.3
  Top Layer w0.254: U1.26@113.38,120.924 113.38,118.669 112.344,117.633 112.344,111.125 114.873,108.596 126.325,108.596 132.004,114.275 v1(144.755,114.275)
  Bottom Layer w0.254: v1(144.755,114.275) 144.755,113.309 MMC.3@147.828,110.236
SCK1: MMC.9 U1.50 | length 39.1
  Top Layer w0.254: U1.50@125.38,120.924 125.38,120.269 139.522,120.269 139.728,120.474 146.911,120.474 148.412,118.974 148.412,115.087 145.796,112.471 142.164,112.471 141.046,111.354 141.046,110.236 MMC.9@140.208,110.236
SPI1_CS0: U1.49
SPI1_SC0: MMC.10
TXD0: U1.82 U7.11 | length 45.2
  Top Layer w0.254: U1.82@122.38,136.124 122.38,138.382 127.787,143.789 v1(139.827,143.789)
  Bottom Layer w0.254: v1(139.827,143.789) 142.494,146.456 142.494,154.864 141.021,156.337 141.021,163.779 U7.11@139.954,164.846
USB_PR: R106.1 R107.2 U1.60 | length 81.7
  Top Layer w0.254: U1.60@126.98,127.024 129.742,127.024 v1(129.743,127.025)
  Bottom Layer w0.254: R106.1@106.68,152.146 106.68,157.226 R107.2@109.22,159.766 114.097,154.889 117.272,154.889 117.272,143.332 115.824,141.884 ; 115.824,141.935 115.824,140.665 117.043,139.446 118.669,139.446 119.101,139.878 119.101,146.533 119.253,146.685 121.107,146.685 122.072,145.72 122.072,144.75 124.104,142.718 124.104,141.046 126.213,138.938 127.711,138.938 136.525,130.124 136.525,128.829 136.093,128.397 131.115,128.397 v1(129.743,127.025)
USB_PUP: R105.1 U1.59 | length 54.9
  Top Layer w0.254: R105.1@89.408,142.494 91.11,144.196 112.776,144.196 113.005,143.967 116.158,143.967 116.844,143.281 120.828,143.281 v1(121.691,142.418) ; v1(125.273,126.118) 125.679,126.524 U1.59@126.98,126.524
  Bottom Layer w0.254: v1(121.691,142.418) 122.098,142.418 123.215,141.3 123.215,140.056 126.873,136.398 126.873,131.445 125.273,129.845 v1(125.273,126.118)
pads on no net: COM.1 COM.4 COM.6 COM.7 COM.8 COM.9 COM.10 COM.11 JTAG.17 JTAG.19 U1.58 U1.63 U1.64 U1.66 U1.67 U1.73 U1.74 U3.1 U5.1 U7.7 U7.8 U7.9 U7.10
copper on no net: | length 10.1
  Top Layer w0.254: 53.569,96.678 53.569,98.5 ; 57.709,97.254 57.709,98.781 ; 84.455,81.362 85.668,82.575 89.383,82.575 90.092,81.866 90.443,81.866

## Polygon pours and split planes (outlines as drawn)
GND on Top Layer (hatched 90Degree grid 0.5 track 1): 169.418,175.082 169.418,77.572 87.478,77.572 87.478,98.196 51.714,98.196 51.714,174.6 51.359,174.955 169.139,174.955
AGND on Top Layer (hatched 90Degree grid 0.5 track 1): 88,98.781 88,77.546 51.918,77.546 51.918,99.746 88.265,99.746
GND on Bottom Layer (hatched 90Degree grid 0.5 track 1): 169.469,174.93 169.469,77.521 86.843,77.521 86.843,97.612 51.994,97.612 51.994,174.727 169.469,174.727
AGND on Bottom Layer (hatched 90Degree grid 0.5 track 1): 52.832,98.349 87.503,98.349 87.503,78.181 52.095,78.181 52.095,98.349

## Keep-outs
Keep-Out Layer:
  lines w0.3: 52.1,77.5 52.1,174.9 169.5,174.9 169.5,77.5 52.1,77.5

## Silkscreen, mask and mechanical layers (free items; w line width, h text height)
Top Overlay:
  text "2008/04/04" at 52.857,94.437 h1.52 r270
  text "MPK" at 55.27,93.904 h1.52 r270
Drill Drawing:
  text ".LEGEND" at 49.642,60.071 h1.52
  text "Drill Drawing." at 49.642,57.531 h1.52

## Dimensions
52.1,77.5 to 52.1,174.9 on Mechanical 1
52.1,77.5 to 169.5,77.5 on Mechanical 1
